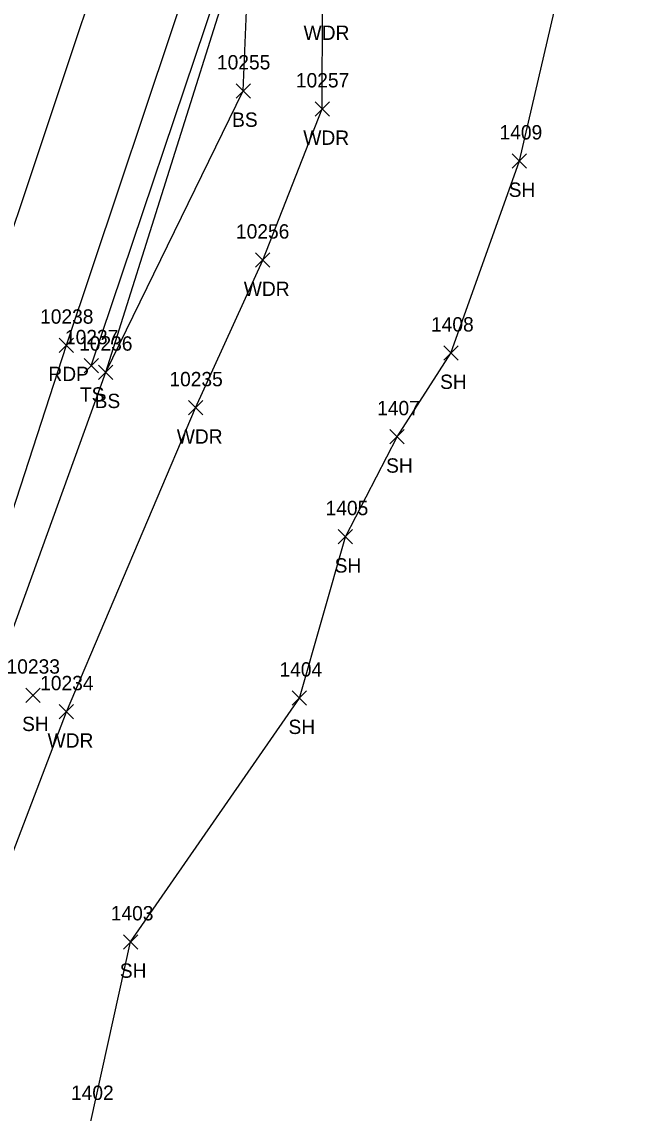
# Model space of a CAD drawing. Extents: x 1651685 to 1653558, y 889533 to 891085.
# Drawn here: x 1652791.5 to 1652876.7, y 890337.8 to 890489.8 of the extents above; entities that cross this region are included whole.
import ezdxf

# ---------------------------------------------------------------- set-up
doc = ezdxf.new("R2010")
doc.units = 0
for name, color, linetype in [('L_A', 7, 'Continuous'), ('L_I', 7, 'Continuous'), ('L_TIC', 7, 'Continuous'), ('LAWA', 7, 'Continuous'), ('LELB', 7, 'Continuous'), ('LSOGP', 7, 'Continuous'), ('P_A', 7, 'Continuous'), ('P_I', 7, 'Continuous'), ('P_TIC', 7, 'Continuous'), ('PET', 7, 'Continuous'), ('PRC', 7, 'Continuous')]:
    doc.layers.add(name, color=color, linetype=linetype)

msp = doc.modelspace()

# ---------------------------------------------------------------- linework, layer by layer
at = {"layer": 'L_TIC'}
for points in [[(1652821.35, 890479.19), (1652823.35, 890481.19)], [(1652823.35, 890479.19), (1652821.35, 890481.19)], [(1652832.35, 890476.68), (1652834.35, 890478.68)], [(1652834.35, 890476.68), (1652832.35, 890478.68)], [(1652859.84, 890469.43), (1652861.84, 890471.43)], [(1652861.84, 890469.43), (1652859.84, 890471.43)], [(1652824.05, 890455.62), (1652826.05, 890457.62)], [(1652826.05, 890455.62), (1652824.05, 890457.62)], [(1652850.28, 890442.67), (1652852.28, 890444.67)], [(1652852.28, 890442.67), (1652850.28, 890444.67)], [(1652800.17, 890440.9), (1652802.17, 890442.9)], [(1652802.17, 890440.9), (1652800.17, 890442.9)], [(1652802.19, 890440), (1652804.19, 890442)], [(1652804.19, 890440), (1652802.19, 890442)], [(1652802.19, 890440), (1652804.19, 890442)], [(1652804.19, 890440), (1652802.19, 890442)], [(1652814.71, 890435.04), (1652816.71, 890437.04)], [(1652816.71, 890435.04), (1652814.71, 890437.04)], [(1652842.77, 890431), (1652844.77, 890433)], [(1652844.77, 890431), (1652842.77, 890433)], [(1652835.59, 890417.08), (1652837.59, 890419.08)], [(1652837.59, 890417.08), (1652835.59, 890419.08)], [(1652792.03, 890395), (1652794.03, 890397)], [(1652794.03, 890395), (1652792.03, 890397)], [(1652829.16, 890394.59), (1652831.16, 890396.59)], [(1652831.16, 890394.59), (1652829.16, 890396.59)], [(1652796.71, 890392.69), (1652798.71, 890394.69)], [(1652798.71, 890392.69), (1652796.71, 890394.69)], [(1652805.65, 890360.62), (1652807.65, 890362.62)], [(1652807.65, 890360.62), (1652805.65, 890362.62)]]:
    msp.add_lwpolyline(points, dxfattribs=at)
at = {"layer": 'LAWA'}
msp.add_lwpolyline([(1652733.24, 890255.05), (1652739.87, 890255.53), (1652757.33, 890267.07), (1652768.84, 890309.36), (1652781.07, 890350.15), (1652797.71, 890393.69), (1652815.71, 890436.04), (1652825.05, 890456.62), (1652833.35, 890477.68), (1652833.39, 890492.3)], dxfattribs=at)
at = {"layer": 'LELB'}
for points in [[(1652801.17, 890441.9), (1652819.95, 890497.78), (1652834.5, 890541.46), (1652846.59, 890562.12), (1652860.39, 890582.03), (1652876.07, 890602.68), (1652893.78, 890623.65), (1652912.56, 890642.08), (1652928.52, 890655.01), (1652947.04, 890668.65), (1652977.97, 890691.06), (1653009.95, 890711.96), (1653047.06, 890737.13), (1653086.67, 890762.46), (1653129.22, 890790.4), (1653161.56, 890810.77), (1653178.09, 890819.36), (1653180.64, 890814.31), (1653173.84, 890802.86)], [(1652803.19, 890441), (1652822.35, 890480.19), (1652822.96, 890495.87), (1652838.19, 890539.83), (1652849.62, 890560.27), (1652863.19, 890579.04), (1652878.87, 890600.11), (1652891.82, 890615.8), (1652896.5, 890621.01), (1652897.47, 890622.7), (1652898.8, 890623.23), (1652915.57, 890639.3), (1652950.1, 890665.22), (1652980.52, 890686.66), (1653013.67, 890707.26), (1653050.87, 890733.01), (1653089.27, 890757.95), (1653133.42, 890785.98), (1653160.95, 890802.08), (1653164.63, 890804.85), (1653167.22, 890806.35), (1653170.81, 890811.17), (1653178.09, 890819.36)], [(1652768.84, 890309.36), (1652773.05, 890352.75), (1652787.7, 890398.23), (1652803.19, 890441), (1652820.95, 890497.33)]]:
    msp.add_lwpolyline(points, dxfattribs=at)
at = {"layer": 'LSOGP'}
msp.add_lwpolyline([(1652801.11, 890336.6), (1652806.65, 890361.62), (1652830.16, 890395.59), (1652836.59, 890418.08), (1652843.77, 890431.99), (1652851.28, 890443.67), (1652860.84, 890470.43), (1652866.91, 890496.63)], dxfattribs=at)
at = {"layer": 'P_TIC'}
for points in [[(1652796.7, 890443.76), (1652798.7, 890445.76)], [(1652798.7, 890443.76), (1652796.7, 890445.76)]]:
    msp.add_lwpolyline(points, dxfattribs=at)
at = {"layer": 'PET'}
msp.add_lwpolyline([(1652703.16, 890284.22), (1652712.04, 890274.26), (1652722.33, 890261.92), (1652735.14, 890284.01), (1652751.62, 890318.12), (1652767.72, 890357.35), (1652783.18, 890400.14), (1652797.7, 890444.76), (1652815.98, 890499.36)], dxfattribs=at)
at = {"layer": 'PRC'}
msp.add_lwpolyline([(1652712.04, 890274.26), (1652722.86, 890292.98), (1652739.69, 890324.96), (1652756.29, 890362.6), (1652772.67, 890406.81), (1652786.21, 890448.94), (1652804.54, 890503.78)], dxfattribs=at)

# ---------------------------------------------------------------- texts
at = {"layer": 'L_A'}
for s, p in [('WDR', (1652830.75, 890487.3)), ('BS', (1652820.79, 890475.19)), ('WDR', (1652830.71, 890472.68)), ('SH', (1652859.33, 890465.43)), ('WDR', (1652822.42, 890451.62)), ('SH', (1652849.77, 890438.67)), ('TS', (1652799.58, 890436.9)), ('BS', (1652801.63, 890436)), ('BS', (1652801.63, 890436)), ('WDR', (1652813.08, 890431.04)), ('SH', (1652842.25, 890427)), ('SH', (1652835.08, 890413.08)), ('SH', (1652791.52, 890391)), ('SH', (1652828.65, 890390.59)), ('WDR', (1652795.07, 890388.69)), ('SH', (1652805.14, 890356.62))]:
    msp.add_text(s, height=2, dxfattribs=at).set_placement(p)
at = {"layer": 'L_I'}
for s, p in [('10255', (1652818.68, 890483.19)), ('10257', (1652829.68, 890480.68)), ('1409', (1652858.06, 890473.43)), ('10256', (1652821.33, 890459.62)), ('1408', (1652848.51, 890446.67)), ('10237', (1652797.5, 890444.9)), ('10236', (1652799.47, 890444)), ('10236', (1652799.47, 890444)), ('10235', (1652812.05, 890439.04)), ('1407', (1652841, 890435)), ('1405', (1652833.82, 890421.08)), ('10233', (1652789.36, 890399)), ('1404', (1652827.39, 890398.59)), ('10234', (1652794.04, 890396.69)), ('1403', (1652803.88, 890364.62)), ('1402', (1652798.34, 890339.6))]:
    msp.add_text(s, height=2, dxfattribs=at).set_placement(p)
at = {"layer": 'P_A'}
msp.add_text('RDP', height=2, dxfattribs=at).set_placement((1652795.19, 890439.76))
at = {"layer": 'P_I'}
msp.add_text('10238', height=2, dxfattribs=at).set_placement((1652794.03, 890447.76))

doc.saveas('drawing.dxf')
